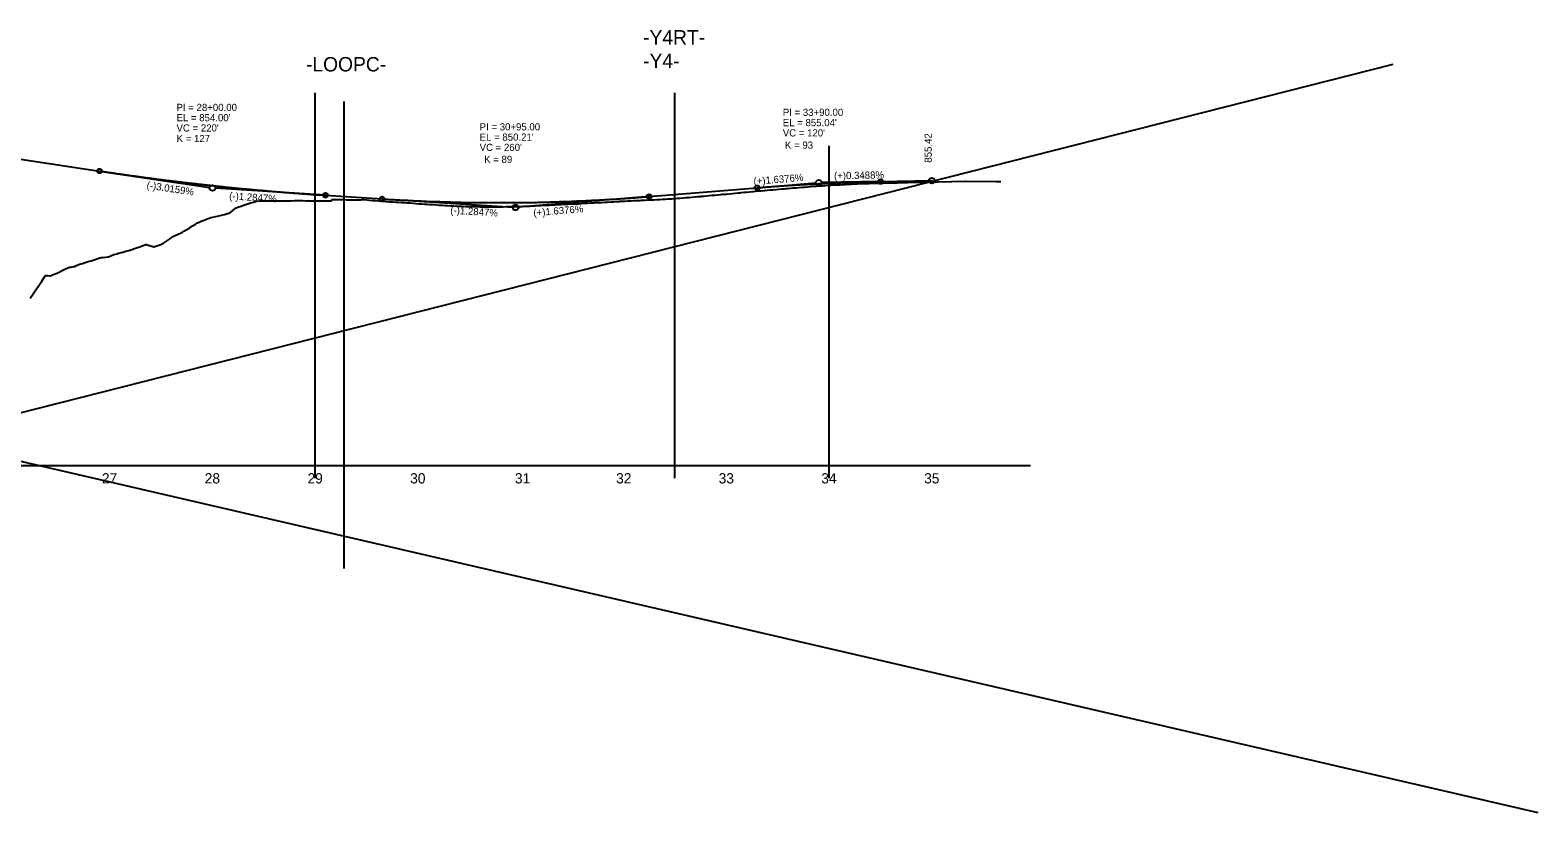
# Model space of a CAD drawing. Extents: x 570622 to 580296, y -55533 to -48575.
# Drawn here: x 575281 to 576748, y -49421 to -48651 of the extents above; entities that cross this region are included whole.
import ezdxf

# ---------------------------------------------------------------- set-up
doc = ezdxf.new("R2010")
doc.units = 0
for name, color, linetype in [('Default', 7, 'Continuous'), ('Exist Profile Cell', 7, 'Continuous'), ('Exist Vertical Profile Ground Line', 7, 'Continuous'), ('Exist Vertical Profile Horizontal Axis Label Major', 7, 'Continuous'), ('Prop Vertical Profile Curve Label', 7, 'Continuous'), ('Prop Vertical Profile Grade', 7, 'Continuous'), ('Prop Vertical Profile Grade Label', 7, 'Continuous'), ('Prop VPI Label', 7, 'Continuous')]:
    doc.layers.add(name, color=color, linetype=linetype)

msp = doc.modelspace()

# ---------------------------------------------------------------- linework, layer by layer
at = {"layer": 'Default'}
for p, q in [((575558.6, -49087.5), (575558.6, -48712.4)), ((575908.6, -49087.5), (575908.6, -48712.4)), ((575586.7, -49175.2), (575586.7, -48720.9)), ((576058.6, -49087.5), (576058.6, -48764)), ((575908.6, -48812.8), (575908.6, -48812.8)), ((575958.6, -48809.5), (575958.6, -48809.5)), ((576008.6, -48804.9), (576008.6, -48804.9)), ((576058.6, -48801), (576058.6, -48801)), ((575808.6, -48819), (575808.6, -48819)), ((575858.6, -48816.3), (575858.6, -48816.3))]:
    msp.add_line(p, q, dxfattribs=at)
at = {"layer": 'Exist Profile Cell'}
for p, q in [((573646, -48694.4), (576748.4, -49412.6)), ((576607.2, -48684.9), (573708.6, -49420.9)), ((573658.6, -49075), (576254.8, -49075))]:
    msp.add_line(p, q, dxfattribs=at)
at = {"layer": 'Exist Vertical Profile Ground Line'}
for points in [[(575901.7, -48815.6), (575902.4, -48815.6), (575905.2, -48815.4), (575908, -48815.2), (575910.8, -48815), (575913.9, -48814.8), (575916.5, -48814.5), (575919.3, -48814.3), (575922.1, -48814.1), (575925, -48813.8), (575927.8, -48813.6), (575930.6, -48813.3), (575933.4, -48813.1), (575934.3, -48813), (575936.3, -48812.8), (575937.1, -48812.8), (575939.1, -48812.6), (575941.9, -48812.3), (575944.7, -48812), (575947.5, -48811.8), (575950.4, -48811.5), (575953.2, -48811.2), (575954.3, -48811.1), (575956, -48811), (575957.7, -48810.9), (575958.8, -48810.8), (575961.7, -48810.5), (575964.5, -48810.3), (575967.3, -48810), (575970.1, -48809.7), (575972.4, -48809.5), (575973, -48809.4), (575975.8, -48809.1), (575978.6, -48808.9), (575981.4, -48808.6), (575984.3, -48808.3), (575985.1, -48808.2), (575987.1, -48808.1), (575989.9, -48807.8), (575992.7, -48807.6), (575995.6, -48807.4), (575996.1, -48807.3), (575998.4, -48807.1), (576001.2, -48806.8), (576004, -48806.6), (576006.8, -48806.3), (576007.3, -48806.3), (576009.7, -48806.1), (576012.5, -48805.8), (576014, -48805.7), (576015.3, -48805.6), (576016.8, -48805.5), (576018.1, -48805.4), (576021, -48805.2), (576023.8, -48804.9), (576024.5, -48804.9), (576026.6, -48804.7), (576029.4, -48804.5), (576032.3, -48804.2), (576035.1, -48804), (576038.1, -48803.8), (576040.7, -48803.6), (576043.6, -48803.3), (576046.4, -48803.1), (576049.2, -48802.9), (576052, -48802.7), (576054.9, -48802.5), (576055.3, -48802.4), (576057.7, -48802.3), (576058.7, -48802.2), (576060.5, -48802.1), (576063.3, -48802), (576066.1, -48801.8), (576069, -48801.7), (576071.8, -48801.6), (576074.6, -48801.4), (576077.4, -48801.3), (576080.3, -48801.1), (576082.5, -48801), (576083.1, -48801), (576085.9, -48800.8), (576088, -48800.7), (576088.7, -48800.7), (576091.8, -48800.6), (576094.4, -48800.5), (576097.2, -48800.5), (576100, -48800.4), (576102.9, -48800.3), (576105.7, -48800.2), (576108.5, -48800.2), (576109.9, -48800.1), (576111.3, -48800.1), (576114.2, -48800), (576117, -48800), (576119.8, -48799.9), (576122.6, -48799.9), (576125.4, -48799.8), (576128.3, -48799.7), (576131.1, -48799.6), (576133.5, -48799.6), (576133.9, -48799.6)], [(576133.9, -48799.6), (576134.4, -48799.6), (576135, -48799.6), (576164.4, -48799), (576165.2, -48798.9), (576191.2, -48798.4), (576192.2, -48798.4), (576221.3, -48798.7), (576225.7, -48798.7)], [(575447.7, -48837.3), (575450.6, -48836.2), (575453.4, -48835.1), (575456.2, -48833.9), (575456.9, -48833.6), (575459, -48833.2), (575461.9, -48832.6), (575464.7, -48832), (575467.5, -48831.3), (575470.3, -48830.6), (575473.1, -48829.9), (575475.3, -48829.3), (575476, -48828.7), (575478.8, -48826.4), (575481, -48824.6), (575481.6, -48824.4), (575484.4, -48823.3), (575486.6, -48822.5), (575487.3, -48822.3), (575490.1, -48821.3), (575491.6, -48820.8), (575492.9, -48820.4), (575495.7, -48819.5), (575498.6, -48818.6), (575501.4, -48817.7), (575501.9, -48817.6), (575504.2, -48817.5), (575507, -48817.5), (575509.9, -48817.5), (575511.9, -48817.4), (575512.7, -48817.4), (575515.5, -48817.5), (575515.9, -48817.5), (575518.3, -48817.5), (575521.2, -48817.4), (575524, -48817.4), (575526.8, -48817.4), (575529.6, -48817.3), (575532.4, -48817.3), (575535.3, -48817.3), (575538.1, -48817.2), (575540.9, -48817.2), (575541.8, -48817.2), (575543.7, -48817.2), (575546.6, -48817.2), (575549.4, -48817.3), (575552.2, -48817.3), (575554.3, -48817.3), (575555, -48817.3), (575557.9, -48817.3), (575560.7, -48817.3), (575563.5, -48817.3), (575564.9, -48817.3), (575566.3, -48817.3), (575569.2, -48817.3), (575572, -48817.3), (575574.4, -48817.3), (575574.8, -48816), (575577.6, -48816), (575580.5, -48816.1), (575583.3, -48816.1), (575586.1, -48816.2), (575588.9, -48816.3), (575591.7, -48816.3), (575594.6, -48816.4), (575597.4, -48816.5), (575598.5, -48816.5), (575599.1, -48816.4), (575600.2, -48816.5), (575603, -48816.3), (575604.7, -48816.1), (575605.9, -48816.2), (575608.7, -48816.5), (575611, -48816.7), (575611.5, -48816.8), (575614.3, -48817), (575617.2, -48817.2), (575620, -48817.4), (575622.8, -48817.7), (575625.6, -48817.9), (575627.7, -48818.1), (575628.5, -48818.1), (575631.3, -48818.3), (575631.7, -48818.4), (575634.1, -48818.5), (575636.9, -48818.7), (575639.8, -48818.8), (575642.6, -48819), (575645.4, -48819.2), (575648.2, -48819.4), (575650.5, -48819.5), (575651, -48819.5), (575653.9, -48819.7), (575656.7, -48820), (575659.5, -48820.2), (575661.4, -48820.3), (575662.3, -48820.4), (575665.2, -48820.6), (575668, -48820.8), (575670, -48820.9), (575670.8, -48821)], [(575670.8, -48821), (575673.6, -48821.1), (575676.5, -48821.3), (575679.3, -48821.5), (575682.1, -48821.7), (575685.2, -48821.9), (575687.8, -48822), (575690.6, -48822.2), (575693.4, -48822.3), (575696.2, -48822.5), (575698.5, -48822.6), (575699.1, -48822.6), (575699.7, -48822.6), (575700.1, -48822.7), (575701.9, -48822.7), (575704.7, -48822.8), (575707.5, -48822.9), (575710.3, -48822.9), (575713.2, -48823), (575716, -48823.1), (575718.8, -48823.2), (575720.2, -48823.2), (575721.6, -48823.2), (575724.5, -48823.2), (575727.3, -48823.2), (575730.1, -48823.2), (575732.9, -48823.2), (575735.8, -48823.2), (575738.6, -48823.2), (575740.6, -48823.2), (575741.4, -48823.2), (575744.2, -48823.1), (575747.1, -48823), (575747.9, -48823), (575749.9, -48823), (575752.7, -48822.9), (575755.5, -48822.8), (575756.6, -48822.8), (575758.4, -48822.8), (575761.2, -48822.7), (575764, -48822.6), (575766.8, -48822.5), (575767.7, -48822.5), (575769.6, -48822.4), (575772.5, -48822.2), (575775.3, -48822.1), (575778.1, -48821.9), (575780, -48821.8), (575780.9, -48821.8), (575783.8, -48821.7), (575786.6, -48821.6), (575789.4, -48821.4), (575792.2, -48821.3), (575795.1, -48821.1), (575797.9, -48821), (575800.7, -48820.8), (575803.5, -48820.7), (575804.3, -48820.6), (575806.4, -48820.5), (575809.2, -48820.4), (575812, -48820.3), (575814.2, -48820.2), (575814.8, -48820.2), (575817.7, -48820), (575820.5, -48819.8), (575823.3, -48819.7), (575826.1, -48819.5), (575828.9, -48819.4), (575830.1, -48819.3), (575831.8, -48819.2), (575833.8, -48819.1), (575834.6, -48819.1), (575837.4, -48818.9), (575840.2, -48818.8), (575843.1, -48818.6), (575845.9, -48818.4), (575848.7, -48818.3), (575851.5, -48818.1), (575852.1, -48818.1), (575854.4, -48818), (575854.9, -48817.9), (575857.2, -48817.8), (575857.9, -48817.8), (575860, -48817.7), (575862.8, -48817.5), (575865.7, -48817.4), (575868.5, -48817.2), (575871.3, -48817.1), (575874.1, -48817), (575875.8, -48816.9), (575877, -48816.8), (575879.8, -48816.7), (575882.6, -48816.5), (575885.4, -48816.4), (575888.2, -48816.3), (575891.1, -48816.1), (575893.9, -48816), (575896.7, -48815.9), (575897.9, -48815.8), (575899.5, -48815.7), (575901.7, -48815.6)], [(575281.1, -48912.1), (575284, -48908), (575286.8, -48903.9), (575289.6, -48899.7), (575292.4, -48895.6), (575295.2, -48891.4), (575296.2, -48890), (575298.1, -48890.2), (575300.6, -48890.5), (575300.9, -48890.4), (575303.7, -48889.2), (575306.5, -48888), (575309.4, -48886.7), (575312.2, -48885.4), (575315, -48884.1), (575317.8, -48882.8), (575319.3, -48882.1), (575320.7, -48881.9), (575323.5, -48881.4), (575324.9, -48881.2), (575326.3, -48880.5), (575329.1, -48879.2), (575329.6, -48879), (575332, -48878.3), (575334.8, -48877.5), (575337.6, -48876.6), (575340.4, -48875.8), (575343.3, -48874.9), (575346.1, -48874), (575348.9, -48873), (575349.8, -48872.7), (575351.7, -48872.5), (575354.5, -48872.2), (575357.4, -48871.8), (575360.2, -48870.7), (575362.6, -48869.8), (575363, -48869.7), (575365.8, -48868.9), (575367.3, -48868.5), (575368.7, -48868.1), (575371.5, -48867.3), (575374.3, -48866.5), (575377.1, -48865.7), (575380, -48864.8), (575382.8, -48863.9), (575385.6, -48863), (575386.9, -48862.6), (575388.4, -48861.9), (575391.3, -48860.8), (575393.5, -48859.9), (575394.1, -48860), (575396.9, -48860.8), (575399.7, -48861.6), (575401.6, -48862.1), (575402.6, -48861.8), (575405.4, -48860.8), (575408.2, -48859.8), (575411, -48858.7), (575413.8, -48856.7), (575416.7, -48854.7), (575419.5, -48852.7), (575420.1, -48852.3), (575422.3, -48851.3), (575425.1, -48850), (575428, -48848.7), (575429.1, -48848.1), (575430.8, -48847.1), (575433.6, -48845.4), (575436.4, -48843.6), (575439.3, -48841.8), (575442.1, -48840), (575443.2, -48839.3), (575444.6, -48838.6), (575444.9, -48838.4), (575447.7, -48837.3)]]:
    msp.add_lwpolyline(points, dxfattribs=at)
at = {"layer": 'Prop Vertical Profile Curve Label'}
for centre in [(575348.6, -48788.4), (576108.6, -48798.7), (575568.6, -48812), (575623.6, -48815.6), (575883.6, -48813.3), (575988.6, -48804.7)]:
    msp.add_circle(centre, 2.25, dxfattribs=at)
at = {"layer": 'Prop Vertical Profile Grade'}
for p, q in [((575228.6, -48770.3), (575348.6, -48788.4)), ((576108.6, -48798.7), (576158.6, -48797.8)), ((575568.6, -48812), (575623.6, -48815.6)), ((575883.6, -48813.3), (575988.6, -48804.7))]:
    msp.add_line(p, q, dxfattribs=at)
for points in [[(575348.6, -48788.4), (575353, -48789), (575357.4, -48789.7), (575361.8, -48790.3), (575366.2, -48791), (575370.6, -48791.6), (575375, -48792.2), (575379.4, -48792.8), (575383.8, -48793.4), (575388.2, -48794), (575392.6, -48794.6), (575397, -48795.2), (575401.4, -48795.8), (575405.8, -48796.4), (575410.2, -48796.9), (575414.6, -48797.5), (575419, -48798), (575423.4, -48798.6), (575427.8, -48799.1), (575432.2, -48799.6), (575436.6, -48800.1), (575441, -48800.6), (575445.4, -48801.1), (575449.8, -48801.6), (575454.2, -48802.1), (575458.6, -48802.6), (575463, -48803.1), (575467.4, -48803.5), (575471.8, -48804), (575476.2, -48804.4), (575480.6, -48804.9), (575485, -48805.3), (575489.4, -48805.7), (575493.8, -48806.1), (575498.2, -48806.5), (575502.6, -48806.9), (575507, -48807.3), (575511.4, -48807.7), (575515.8, -48808.1), (575520.2, -48808.5), (575524.6, -48808.8), (575529, -48809.2), (575533.4, -48809.5), (575537.8, -48809.9), (575542.2, -48810.2), (575546.6, -48810.5), (575551, -48810.8), (575555.4, -48811.2), (575559.8, -48811.5), (575564.2, -48811.7), (575568.6, -48812)], [(575988.6, -48804.7), (575991, -48804.5), (575993.4, -48804.3), (575995.8, -48804.1), (575998.2, -48803.9), (576000.6, -48803.7), (576003, -48803.6), (576005.4, -48803.4), (576007.8, -48803.2), (576010.2, -48803), (576012.6, -48802.9), (576015, -48802.7), (576017.4, -48802.5), (576019.8, -48802.4), (576022.2, -48802.2), (576024.6, -48802.1), (576027, -48801.9), (576029.4, -48801.8), (576031.8, -48801.6), (576034.2, -48801.5), (576036.6, -48801.4), (576039, -48801.2), (576041.4, -48801.1), (576043.8, -48801), (576046.2, -48800.8), (576048.6, -48800.7), (576051, -48800.6), (576053.4, -48800.5), (576055.8, -48800.4), (576058.2, -48800.3), (576060.6, -48800.2), (576063, -48800.1), (576065.4, -48800), (576067.8, -48799.9), (576070.2, -48799.8), (576072.6, -48799.7), (576075, -48799.6), (576077.4, -48799.5), (576079.8, -48799.4), (576082.2, -48799.4), (576084.6, -48799.3), (576087, -48799.2), (576089.4, -48799.2), (576091.8, -48799.1), (576094.2, -48799), (576096.6, -48799), (576099, -48798.9), (576101.4, -48798.9), (576103.8, -48798.8), (576106.2, -48798.8), (576108.6, -48798.7)], [(575623.6, -48815.6), (575628.8, -48815.9), (575634, -48816.2), (575639.2, -48816.5), (575644.4, -48816.8), (575649.6, -48817), (575654.8, -48817.3), (575660, -48817.5), (575665.2, -48817.8), (575670.4, -48818), (575675.6, -48818.1), (575680.8, -48818.3), (575686, -48818.5), (575691.2, -48818.6), (575696.4, -48818.8), (575701.6, -48818.9), (575706.8, -48819), (575712, -48819), (575717.2, -48819.1), (575722.4, -48819.2), (575727.6, -48819.2), (575732.8, -48819.2), (575738, -48819.2), (575743.2, -48819.2), (575748.4, -48819.2), (575753.6, -48819.2), (575758.8, -48819.1), (575764, -48819), (575769.2, -48819), (575774.4, -48818.9), (575779.6, -48818.7), (575784.8, -48818.6), (575790, -48818.5), (575795.2, -48818.3), (575800.4, -48818.1), (575805.6, -48818), (575810.8, -48817.7), (575816, -48817.5), (575821.2, -48817.3), (575826.4, -48817), (575831.6, -48816.8), (575836.8, -48816.5), (575842, -48816.2), (575847.2, -48815.9), (575852.4, -48815.6), (575857.6, -48815.2), (575862.8, -48814.9), (575868, -48814.5), (575873.2, -48814.1), (575878.4, -48813.7), (575883.6, -48813.3)]]:
    msp.add_spline(points, degree=3, dxfattribs=at)
at = {"layer": 'Prop VPI Label'}
for p, q in [((575348.6, -48788.4), (575455.9, -48804.6)), ((575988.6, -48804.7), (576045.9, -48800)), ((576108.6, -48798.7), (576051.4, -48799.7)), ((575568.6, -48812), (575461.4, -48805.1)), ((575883.6, -48813.3), (575756.4, -48823.7)), ((575623.6, -48815.6), (575750.9, -48823.7))]:
    msp.add_line(p, q, dxfattribs=at)
for centre in [(576048.6, -48799.8), (576158.6, -48797.8), (576158.6, -48797.8), (575458.6, -48805), (575753.6, -48823.9)]:
    msp.add_circle(centre, 2.75, dxfattribs=at)

# ---------------------------------------------------------------- texts
at = {"layer": 'Exist Profile Cell'}
for s, p in [('-Y4RT-', (575877.7, -48665.3)), ('-LOOPC-', (575549.6, -48691.5)), ('-Y4-', (575877.7, -48688.1))]:
    msp.add_text(s, height=14, dxfattribs=at).set_placement(p)
at = {"layer": 'Exist Vertical Profile Horizontal Axis Label Major'}
for s, p in [('27', (575351, -49092.5)), ('28', (575451.1, -49092.5)), ('29', (575551.1, -49092.5)), ('30', (575651, -49092.5)), ('31', (575752.9, -49092.5)), ('32', (575851.4, -49092.5)), ('33', (575951.2, -49092.5)), ('34', (576051.1, -49092.5)), ('35', (576151.2, -49092.5))]:
    msp.add_text(s, height=10, dxfattribs=at).set_placement(p)
at = {"layer": 'Prop Vertical Profile Curve Label'}
for s, p in [("VC = 220'", (575423.6, -48750)), ('K = 127', (575423.7, -48760.3)), ("VC = 120'", (576013.6, -48754.8)), ("VC = 260'", (575718.6, -48768.9)), ('K = 93', (576015.8, -48766.7)), ('K = 89', (575723, -48780.6))]:
    msp.add_text(s, height=7, dxfattribs=at).set_placement(p)
at = {"layer": 'Prop Vertical Profile Grade Label'}
for s, rotation, p in [('(-)3.0159%', 351.4247, (575394.2, -48805.4)), ('(+)1.6376%', 4.681, (575985.4, -48801.9)), ('(+)0.3488%', 0.9992, (576063.5, -48796.5)), ('(-)1.2847%', 356.3245, (575474.7, -48816)), ('(-)1.2847%', 356.3245, (575689.9, -48829.8)), ('(+)1.6376%', 4.681, (575771.2, -48832.5))]:
    msp.add_text(s, height=7, rotation=rotation, dxfattribs=at).set_placement(p)
at = {"layer": 'Prop VPI Label'}
for s, p in [('PI = 28+00.00', (575423.6, -48730)), ("EL = 854.00'", (575423.6, -48740)), ('PI = 30+95.00', (575718.6, -48748.9)), ('PI = 33+90.00', (576013.6, -48734.8)), ("EL = 855.04'", (576013.6, -48744.8)), ("EL = 850.21'", (575718.6, -48758.9))]:
    msp.add_text(s, height=7, dxfattribs=at).set_placement(p)
msp.add_text('855.42', height=7, rotation=90, dxfattribs=at).set_placement((576158.6, -48780.3))
msp.add_text('855.42', height=7, rotation=90, dxfattribs=at).set_placement((576158.6, -48780.3))

doc.saveas('drawing.dxf')
